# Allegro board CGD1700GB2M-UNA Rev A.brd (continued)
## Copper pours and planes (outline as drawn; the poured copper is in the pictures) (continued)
+20V_LS on BOTTOM: 12.31,16.76 13.11,16.76 13.57,17.21 13.57,19.01 12.62,19.01 12.62,17.7 12.31,17.39
+20V_LS on LAYER3: 6.98,21.46 6.81,21.39 6.73,21.21 6.73,19.15 6.78,18.92 6.91,18.72 12.37,13.26 12.57,13.13 12.8,13.08 16.26,13.08 16.44,13.16 16.51,13.33 16.51,16.45 16.46,16.68 16.33,16.88 11.93,21.28 11.73,21.42 11.49,21.46
-5V_LS on BOTTOM: 16.94,20.19 16.76,20.12 16.69,19.94 16.69,16.26 16.76,16.08 16.94,16 19.06,16 19.29,15.96 19.49,15.82 19.94,15.37 23.11,15.37 23.35,15.41 23.55,15.55 23.7,15.7 23.83,15.89 23.88,16.13 23.88,17.78 23.8,17.96 23.62,18.03 21.72,18.03 21.5,18.25 21.5,19.94 21.42,20.12 21.24,20.19
-5V_LS on LAYER3: 6.98,26.42 6.81,26.34 6.73,26.16 6.73,24.31 6.81,24.13 6.98,24.05 9.22,24.05 9.45,24.01 9.65,23.87 17.73,15.8 17.93,15.67 18.16,15.62 20.19,15.62 20.43,15.67 20.63,15.8 21.28,16.46 21.42,16.66 21.46,16.89 21.46,26.16 21.39,26.34 21.21,26.42
0 on TOP: 0.76,41.78 0.58,41.71 0.51,41.53 0.51,37.59 0.58,37.41 0.76,37.34 4.83,37.34 5.01,37.41 5.08,37.59 5.08,41.53 5.01,41.71 4.83,41.78
0 on BOTTOM: 5.59,44.7 5.41,44.63 5.33,44.45 5.33,39.88 5.26,39.7 5.08,39.62 0.76,39.62 0.58,39.55 0.51,39.37 0.51,37.58 0.58,37.4 0.76,37.33 9.96,37.33 10.14,37.25 10.21,37.07 10.21,32.26 10.29,32.08 10.47,32 13.74,32 13.92,32.08 13.99,32.26 13.99,43.28 14.04,43.52 14.17,43.72 14.3,43.84 14.43,44.04 14.48,44.28 14.48,44.45 14.4,44.63 14.22,44.7
0 on LAYER2: 8.25,58.93 8.33,59.11 8.51,59.18 42.29,59.18 42.47,59.11 42.55,58.93 42.55,55.44 43.72,52.61 46.55,51.44 50.04,51.44 50.22,51.36 50.29,51.18 50.29,32.26 50.22,32.08 50.04,32 0.76,32 0.58,32.08 0.51,32.26 0.51,51.18 0.58,51.36 0.76,51.44 4.25,51.44 7.08,52.61 8.25,55.44 ; 3 cut-outs
HS-DM on TOP: 45.77,14.79 49.58,14.79 49.58,11.56 45.77,11.56
HS-DM on BOTTOM: 45.77,12.19 49.58,12.19 49.58,8.94 45.77,8.94
HS-DRAIN on TOP, LAYER2, LAYER3: 50.29,8.06 50.18,8.33 49.91,8.44 45.44,8.44 45.17,8.33 45.06,8.06 45.06,0.89 45.17,0.62 45.44,0.51 49.91,0.51 50.18,0.62 50.29,0.89
HS-DRAIN on BOTTOM: 45.31,4.7 45.13,4.62 45.06,4.45 45.06,0.89 45.17,0.62 45.44,0.51 49.91,0.51 50.18,0.62 50.29,0.89 50.29,4.45 50.22,4.62 50.04,4.7
HS-GATE on TOP: 29.4,4.25 29.16,5.63 28.45,6.85 28.45,11.81 28.52,11.99 28.7,12.06 41.27,12.06 41.45,11.99 41.53,11.81 41.53,0.76 41.45,0.58 41.27,0.5 29.66,0.51 29.48,0.58 29.4,0.76
HS-SOURCE on TOP: 31.08,26.42 30.9,26.34 30.82,26.16 30.82,22.1 30.9,21.92 31.08,21.84 31.33,21.84 31.51,21.92 31.58,22.1 31.58,26.16 31.51,26.34 31.33,26.42
HS-SOURCE on BOTTOM: 31.6,22.3 31.6,23.82 31.52,24 31.34,24.08 31.24,24.08 31.06,24 30.99,23.82 30.99,22.3 29.26,22.3 29.26,21.29 33.32,21.29 33.32,22.3
HS-SOURCE on BOTTOM: 41.03,15.17 42.67,15.17 42.85,15.1 42.93,14.92 42.93,10.92 42.85,10.74 42.67,10.67 41.78,10.67 41.6,10.59 41.53,10.41 41.53,0.76 41.45,0.58 41.27,0.5 29.66,0.5 29.48,0.58 29.4,0.76 29.4,4.25 28.76,6.42 27.05,7.9 27.05,11.87 27.13,12.05 27.3,12.12 34.37,12.12 34.55,12.05 34.62,11.87 34.62,7.82 34.69,7.64 34.87,7.57 38.3,7.57 38.54,7.62 38.74,7.75 39.06,8.08 39.2,8.27 39.24,8.51 39.24,10.05 39.32,10.23 39.5,10.31 40.18,10.31 40.36,10.38 40.44,10.56 40.44,11.35 40.48,11.59 40.62,11.79 42.11,13.28 42.11,13.62 42.04,13.8 41.86,13.87 41.29,13.87 41.11,13.95 41.03,14.13
HS-SOURCE on LAYER2: 27.05,7.9 28.76,6.42 29.4,4.25 29.4,0.76 29.47,0.58 29.65,0.51 41.27,0.51 41.45,0.58 41.53,0.76 41.53,13.72 41.58,13.95 41.71,14.15 43.38,15.82 43.58,15.96 43.81,16 50.04,16 50.22,16.08 50.29,16.26 50.29,26.16 50.22,26.34 50.04,26.42 27.3,26.42 27.13,26.34 27.05,26.16 ; 1 cut-out
HS-VDD on TOP: 33.62,26.04 33.44,25.96 33.36,25.78 33.36,23.16 33.44,22.99 33.62,22.91 33.87,22.91 34.05,22.99 34.12,23.16 34.12,25.78 34.05,25.96 33.87,26.04
HS-VDD on BOTTOM: 36.35,18.9 36.48,18.7 36.52,18.47 36.52,15.95 36.48,15.72 36.35,15.52 34.8,13.97 34.67,13.77 34.62,13.54 34.62,12.55 34.55,12.37 34.37,12.3 32.66,12.3 31.04,13.92 31.04,14.18 31.39,14.54 31.39,15.17 31.22,15.35 27.3,15.35 27.13,15.43 27.05,15.61 27.05,16.85 27.13,17.03 27.3,17.1 29.27,17.1 29.27,19.62 28.42,20.47 27.3,20.47 27.13,20.55 27.05,20.73 27.05,26.16 27.13,26.34 27.3,26.42 33.98,26.42 34.16,26.34 34.24,26.16 34.24,21.26 34.29,21.03 34.42,20.83
HS-VDD on LAYER3: 34.37,26.42 34.55,26.34 34.62,26.16 34.62,22.35 34.58,22.12 34.44,21.92 32.45,19.92 32.31,19.72 32.27,19.49 32.27,18.3 32.31,18.07 32.45,17.87 33.3,17.02 33.5,16.89 33.73,16.84 34.67,16.84 34.85,16.77 34.92,16.59 34.92,12.45 34.85,12.27 34.67,12.19 27.3,12.19 27.13,12.27 27.05,12.45 27.05,26.16 27.13,26.34 27.3,26.42
HS-VSS on BOTTOM: 34.42,26.16 34.49,26.34 34.67,26.42 43.31,26.42 43.49,26.34 43.56,26.16 43.56,23.29 43.49,23.11 43.31,23.04 40.72,23.04 40.54,22.96 40.46,22.78 40.46,20.63 40.39,20.45 40.21,20.37 38.68,20.37 38.5,20.3 38.43,20.12 38.43,15.44 38.5,15.26 38.68,15.19 40.34,15.19 40.34,13.9 36.05,13.9 35.87,13.82 35.8,13.64 35.8,12.12 40.26,12.12 40.26,10.79 40.18,10.62 40,10.54 39.24,10.54 39.06,10.47 38.99,10.29 38.99,8.51 38.94,8.27 38.81,8.08 38.66,7.93 38.46,7.79 38.23,7.75 35.05,7.75 34.87,7.82 34.8,8 34.8,13.46 34.84,13.7 34.98,13.9 36.52,15.44 36.66,15.64 36.7,15.87 36.7,18.54 36.66,18.78 36.52,18.98 34.6,20.9 34.46,21.1 34.42,21.34
LS-DM on TOP: 1.22,14.79 5.03,14.79 5.03,11.56 1.22,11.56
LS-DM on BOTTOM: 1.22,12.19 5.03,12.19 5.03,8.94 1.22,8.94
LS-DRAIN on TOP, LAYER2, LAYER3: 0.51,8.06 0.62,8.33 0.89,8.44 5.36,8.44 5.63,8.33 5.74,8.06 5.74,0.89 5.63,0.62 5.36,0.51 0.89,0.51 0.62,0.62 0.51,0.89
LS-DRAIN on BOTTOM: 5.49,4.7 5.67,4.62 5.74,4.45 5.74,0.89 5.63,0.62 5.36,0.51 0.89,0.51 0.62,0.62 0.51,0.89 0.51,4.45 0.58,4.62 0.76,4.7
LS-GATE on TOP: 22.1,12.06 22.28,11.99 22.35,11.81 22.35,6.85 21.65,5.63 21.4,4.25 21.4,0.76 21.33,0.58 21.15,0.51 9.52,0.51 9.35,0.58 9.27,0.76 9.27,11.81 9.35,11.99 9.52,12.06
LS-SOURCE on TOP: 15.66,26.04 15.48,25.96 15.41,25.78 15.41,23.16 15.48,22.99 15.66,22.91 15.91,22.91 16.09,22.99 16.17,23.16 16.17,25.78 16.09,25.96 15.91,26.04
LS-SOURCE on BOTTOM: 16.33,24.37 16.33,26.16 16.26,26.34 16.08,26.42 12.54,26.42 12.54,24.37
LS-SOURCE on BOTTOM: 19.2,23.14 19.4,23.27 19.63,23.32 23.62,23.32 23.8,23.24 23.88,23.06 23.88,18.47 23.8,18.29 23.62,18.21 23.17,18.21 22.29,17.34 21.87,17.34 21.87,18.36 21.68,18.56 21.68,20.12 21.6,20.3 21.42,20.37 16.94,20.37 16.76,20.45 16.69,20.63 16.69,22.05 16.76,22.23 16.94,22.3 18.36,22.3
LS-SOURCE on BOTTOM: 11.99,20.77 11.99,17.68 11.01,16.69 10.64,16.69 10.64,16.3 10.57,16.12 10.39,16.04 7.87,16.04 7.69,16.12 7.62,16.3 7.62,18.03 7.69,18.21 7.87,18.29 9.91,18.29 9.91,20.51 9.98,20.69 10.16,20.77
LS-SOURCE on LAYER2: 23.62,26.42 23.8,26.34 23.88,26.16 23.88,7.95 22.08,6.48 21.4,4.25 21.4,0.76 21.33,0.58 21.15,0.51 9.52,0.51 9.35,0.58 9.27,0.76 9.27,13.84 9.22,14.08 9.09,14.28 7.55,15.82 7.35,15.96 7.11,16 0.76,16 0.58,16.08 0.51,16.26 0.51,26.16 0.58,26.34 0.76,26.42
LS-SOURCE on LAYER3: 23.88,15.62 23.88,7.95 22.08,6.48 21.4,4.25 21.4,0.76 21.32,0.58 21.15,0.51 9.52,0.51 9.35,0.58 9.27,0.76 9.27,13.84 9.22,14.08 9.09,14.28 7.55,15.82 7.35,15.96 7.11,16 0.76,16 0.58,16.08 0.51,16.26 0.51,26.16 0.58,26.34 0.76,26.42 6.3,26.42 6.48,26.34 6.55,26.16 6.55,24.31 7.17,24.31 7.17,21.64 7.16,21.64 6.55,21.03 6.55,18.09 11.86,12.78 20.78,12.78 21.01,12.82 21.21,12.96
LS-VDD on TOP: 18.2,26.04 18.02,25.96 17.95,25.78 17.95,23.16 18.02,22.99 18.2,22.91 18.45,22.91 18.63,22.99 18.71,23.16 18.71,25.78 18.63,25.96 18.45,26.04
LS-VDD on BOTTOM: 18.67,26.42 18.85,26.34 18.92,26.16 18.92,23.37 18.88,23.13 18.74,22.93 18.47,22.66 18.27,22.53 18.03,22.48 16.76,22.48 16.58,22.41 16.51,22.23 16.51,15.87 16.44,15.7 16.26,15.62 14.43,15.62 14.25,15.55 14.17,15.37 14.17,12.14 12.25,12.14 12.25,14.73 10.82,14.73 10.82,16.51 12.86,16.51 13.1,16.56 13.29,16.69 13.54,16.93 13.67,17.13 13.72,17.37 13.72,20.7 13.64,20.88 13.46,20.95 10.16,20.95 9.98,21.03 9.91,21.21 9.91,22.1 9.98,22.28 10.16,22.35 13.33,22.35 13.33,23.24 14.07,23.98 14.27,24.11 14.5,24.15 16.38,24.15 16.56,24.23 16.64,24.41 16.64,26.16 16.71,26.34 16.89,26.42
LS-VSS on TOP: 22.01,26.04 21.83,25.96 21.76,25.78 21.76,23.75 21.83,23.57 22.01,23.49 23.62,23.49 23.8,23.57 23.88,23.75 23.88,25.78 23.8,25.96 23.62,26.04
LS-VSS on BOTTOM: 23.62,26.42 23.8,26.34 23.88,26.16 23.88,23.75 23.8,23.57 23.62,23.49 19.36,23.49 19.18,23.57 19.1,23.75 19.1,26.16 19.18,26.34 19.36,26.42
LS-VSS on BOTTOM: 21.18,15.17 19.89,15.17 19.41,15.64 19.22,15.78 18.98,15.82 16.94,15.82 16.76,15.75 16.69,15.57 16.69,13.39 16,12.7 15.8,12.57 15.57,12.52 14.6,12.52 14.43,12.45 14.35,12.27 14.35,10.41 14.4,10.18 14.53,9.98 16.58,7.93 16.78,7.79 17.02,7.75 19.18,7.75 19.36,7.82 19.43,8 19.43,10.74 19.36,10.92 19.18,11 16.97,11 16.79,11.07 16.71,11.25 16.71,11.91 16.76,12.15 16.89,12.35 17.32,12.77 21.15,12.77 21.15,14.51 21.18,14.54
LS-VSS on LAYER3: 21.64,26.16 21.72,26.34 21.9,26.42 23.62,26.42 23.8,26.34 23.88,26.16 23.88,16.13 23.83,15.89 23.7,15.7 21.13,13.13 20.94,13 20.7,12.95 18.03,12.95 17.85,13.03 17.78,13.21 17.78,15.19 17.85,15.37 18.03,15.44 20.27,15.44 20.5,15.49 20.7,15.62 21.46,16.38 21.59,16.58 21.64,16.82
MILLERCLAMP-HS on TOP: 41.53,18.31 41.48,18.55 41.35,18.75 36.84,23.25 36.71,23.45 36.66,23.69 36.66,25.78 36.59,25.96 36.41,26.04 36.16,26.04 35.98,25.96 35.9,25.78 35.9,23.47 35.95,23.23 36.08,23.03 38.17,20.94 38.31,20.74 38.35,20.51 38.35,13.21 38.43,13.03 38.61,12.95 41.27,12.95 41.45,13.03 41.53,13.21
MILLERCLAMP-LS on TOP: 23.88,20.55 23.83,20.78 23.7,20.98 21.43,23.25 21.29,23.45 21.25,23.69 21.25,25.78 21.17,25.96 20.99,26.04 20.74,26.04 20.56,25.96 20.49,25.78 20.49,23.47 20.53,23.23 20.66,23.03 21.97,21.73 22.16,21.44 22.23,21.11 22.23,17.97 22.18,17.74 22.05,17.54 19.61,15.1 19.48,14.9 19.43,14.67 19.43,13.21 19.51,13.03 19.68,12.95 22.1,12.95 22.28,13.03 22.35,13.21 22.35,14.1 22.4,14.33 22.53,14.53 23.7,15.7 23.83,15.89 23.88,16.13
UNPROTECTED_VIN on BOTTOM: 33.02,58.55 32.84,58.47 32.77,58.29 32.77,57.53 32.81,57.3 32.95,57.1 34.04,56.01 34.04,55.88 35.25,54.66 35.39,54.46 35.43,54.23 35.43,43.43 35.51,43.25 35.69,43.18 38.35,43.18 38.53,43.25 38.61,43.43 38.61,44.7 41.73,47.83 41.86,48.03 41.91,48.26 41.91,58.29 41.84,58.47 41.66,58.55
VOUT_OFF_HS on TOP: 38.1,20.4 38.05,20.63 37.92,20.83 35.57,23.18 35.44,23.38 35.39,23.61 35.39,25.78 35.32,25.96 35.14,26.04 34.89,26.04 34.71,25.96 34.63,25.78 34.63,22.27 34.68,22.03 34.81,21.83 35.48,21.16 35.67,20.88 35.74,20.55 35.74,18.05 35.69,17.82 35.56,17.62 33.71,15.77 33.58,15.57 33.53,15.34 33.53,14.2 33.6,14.02 33.78,13.95 37.85,13.95 38.03,14.02 38.1,14.2
N5777665 on TOP: 44.45,44.65 44.52,44.83 44.7,44.91 50.04,44.91 50.22,44.83 50.29,44.65 50.29,42.37 50.22,42.19 50.04,42.11 47.12,42.11 46.94,42.04 46.86,41.86 46.86,39.88 46.91,39.64 47.04,39.44 48.87,37.62 49,37.42 49.05,37.19 49.05,34.8 48.97,34.62 48.79,34.54 44.7,34.54 44.52,34.62 44.45,34.8
N5777665 on BOTTOM: 48.89,37.21 49.07,37.14 49.15,36.96 49.15,34.8 49.07,34.62 48.89,34.54 41.91,34.54 41.73,34.62 41.66,34.8 41.66,36.96 41.73,37.14 41.91,37.21
N5777737 on TOP: 47.37,41.86 47.19,41.78 47.12,41.6 47.12,40 47.16,39.77 47.3,39.57 49.12,37.75 49.26,37.55 49.3,37.31 49.3,34.29 49.23,34.11 49.05,34.04 44.7,34.04 44.52,33.96 44.45,33.78 44.45,32.26 44.52,32.08 44.7,32 50.04,32 50.22,32.08 50.29,32.26 50.29,41.6 50.22,41.78 50.04,41.86
N5777737 on BOTTOM: 48.89,34.29 49.07,34.22 49.15,34.04 49.15,32.26 49.07,32.08 48.89,32 41.91,32 41.73,32.08 41.66,32.26 41.66,34.04 41.73,34.22 41.91,34.29
N5778706 on TOP: 5.33,44.42 5.41,44.6 5.59,44.68 10.92,44.68 11.1,44.6 11.18,44.42 11.18,42.37 11.1,42.19 10.92,42.11 8,42.11 7.82,42.04 7.75,41.86 7.75,39.88 7.79,39.64 7.93,39.44 9.75,37.62 9.88,37.42 9.93,37.19 9.93,34.8 9.86,34.62 9.68,34.54 5.59,34.54 5.41,34.62 5.33,34.8
N5778706 on BOTTOM: 9.78,37.15 9.96,37.08 10.03,36.9 10.03,34.8 9.96,34.62 9.78,34.54 2.79,34.54 2.61,34.62 2.54,34.8 2.54,36.9 2.61,37.08 2.79,37.15
N5778794 on TOP: 8.26,41.86 8.08,41.78 8,41.6 8,40 8.05,39.77 8.18,39.57 10.01,37.75 10.14,37.55 10.19,37.31 10.19,34.29 10.11,34.11 9.93,34.04 5.59,34.04 5.41,33.96 5.33,33.78 5.33,32.26 5.41,32.08 5.59,32 10.92,32 11.1,32.08 11.18,32.26 11.18,41.6 11.1,41.78 10.92,41.86
N5778794 on BOTTOM: 9.78,34.29 9.96,34.22 10.03,34.04 10.03,32.26 9.96,32.08 9.78,32 2.79,32 2.61,32.08 2.54,32.26 2.54,34.04 2.61,34.22 2.79,34.29
N5780153 on TOP: 4.83,49.66 5.01,49.58 5.08,49.4 5.08,42.29 5.01,42.11 4.83,42.04 0.76,42.04 0.58,42.11 0.51,42.29 0.51,49.4 0.58,49.58 0.76,49.66
N6067568 on BOTTOM: 30.72,15.17 30.72,12.3 27.3,12.3 27.13,12.37 27.05,12.55 27.05,15.17
N6067584 on BOTTOM: 7.87,15.24 7.69,15.17 7.62,14.99 7.62,13.39 7.67,13.16 7.8,12.96 8.44,12.32 8.64,12.18 8.87,12.14 11.94,12.14 11.94,13.84 11.57,14.21 11.57,14.55 10.64,14.55 10.64,14.99 10.57,15.17 10.39,15.24
N6093449 on TOP: 39.75,49.4 39.83,49.58 40,49.66 43.94,49.66 44.12,49.58 44.2,49.4 44.2,42.37 44.12,42.19 43.94,42.11 40,42.11 39.83,42.19 39.75,42.37

Small or netless copper shapes (teardrops, artwork), in the pictures only: 5 on TOP, 6 on BOTTOM, 2 on LAYER3

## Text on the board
Ref Des/Silkscreen Bottom: REV A | XGD1700HB2M-FM3
User.Comments: 258.3 mils | S | LS | 0.100" Pitch | G | HS | .17 | 1.06 | 4.4 | 27 | 2.00 | INCHES [mm] | 50.8 | 2.35 | 59.7
Ref Des/Silkscreen Top: S | ON | G | LOW-SIDE | OFF | MC | HIGH-SIDE | L | A | Y | P | O | C | I | T | N
DISPLAY_BOTTOM: FIGURE | FINISHED_SIZE | 13.0 | 35.0 | 40.0 | 45.0 | 65.0 | 175.0 | DRILL CHART: TOP to BOTTOM | ALL UNITS ARE IN MILS | PLATED | NON-PLATED | QTY | 171 | 10 | 26 | 2 | 3 | 222 | TOTAL HOLES:
